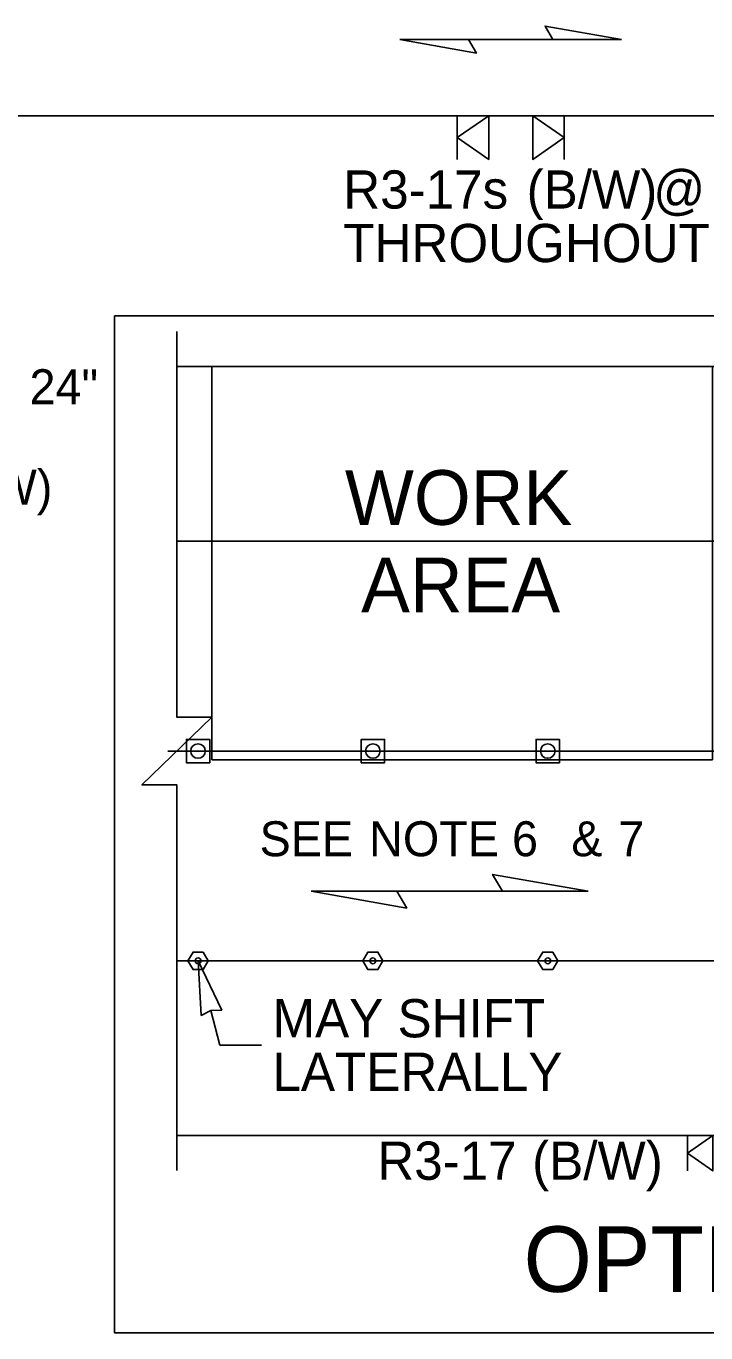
# Model space of a CAD drawing. Extents: x 99999.1 to 100095.7, y 99995 to 100010.7.
# Drawn here: x 100045 to 100046.244, y 100003.505 to 100005.896 of the extents above; entities that cross this region are included whole.
import ezdxf

# ---------------------------------------------------------------- set-up
doc = ezdxf.new("R2010")
doc.units = 0
for name, color, linetype in [('RD_ED_ShoulderPavedEdge', 7, 'Continuous'), ('RD_MK_LineEdgeWhite', 7, 'Continuous'), ('RD_MK_LineSkipCenter', 7, 'Continuous'), ('SH_DE_DetailHeading2Text', 7, 'Continuous'), ('SH_TI_Tables', 7, 'Continuous'), ('TR_SN_ConstructionSigns', 7, 'Continuous'), ('TR_WZ_PortableSignMountBlk-Wht', 7, 'Continuous'), ('TR_WZ_TrafficCone', 7, 'Continuous'), ('TR_WZ_TubularMarker', 7, 'Continuous'), ('TR_WZ_WorkAreaLabel', 7, 'Continuous'), ('TR_WZ_WorkZoneDetails', 7, 'Continuous'), ('TR_WZ_WorkZoneTextCurrent', 7, 'Continuous')]:
    doc.layers.add(name, color=color, linetype=linetype)

msp = doc.modelspace()

# ---------------------------------------------------------------- linework, layer by layer
at = {"layer": 'RD_ED_ShoulderPavedEdge'}
for p, q in [((100040.1076, 100005.7323), (100055.6424, 100005.7323)), ((100045.2759, 100005.2735), (100049.1933, 100005.2735)), ((100045.2759, 100003.8655), (100049.1933, 100003.8655))]:
    msp.add_line(p, q, dxfattribs=at)
at = {"layer": 'RD_MK_LineEdgeWhite'}
for p, q in [((100045.2759, 100004.9535), (100049.1933, 100004.9535)), ((100045.2759, 100004.1855), (100049.1933, 100004.1855))]:
    msp.add_line(p, q, dxfattribs=at)
at = {"layer": 'RD_MK_LineSkipCenter'}
msp.add_lwpolyline([(100049.1767, 100004.5695), (100045.2594, 100004.5695)], dxfattribs=at)
at = {"layer": 'SH_TI_Tables'}
msp.add_lwpolyline([(100045.1619, 100005.3662), (100049.3073, 100005.3662), (100049.3073, 100003.5045), (100045.1619, 100003.5045)], close=True, dxfattribs=at)
at = {"layer": 'TR_WZ_PortableSignMountBlk-Wht'}
for p, q in [((100045.7891, 100005.6523), (100045.7891, 100005.7323)), ((100045.9846, 100005.6523), (100045.9846, 100005.7323)), ((100046.2103, 100003.8011), (100046.2103, 100003.8655))]:
    msp.add_line(p, q, dxfattribs=at)
for points in [[(100045.7891, 100005.6923), (100045.8465, 100005.7323), (100045.8465, 100005.6523)], [(100045.9846, 100005.6923), (100045.9271, 100005.7323), (100045.9271, 100005.6523)], [(100046.2103, 100003.8333), (100046.2565, 100003.8655), (100046.2565, 100003.8011)]]:
    msp.add_lwpolyline(points, close=True, dxfattribs=at)
at = {"layer": 'TR_WZ_TrafficCone'}
for points in [[(100045.2933, 100004.5908), (100045.3359, 100004.5908), (100045.3359, 100004.5482), (100045.2933, 100004.5482), (100045.2933, 100004.5908)], [(100045.2933, 100004.5482), (100045.3359, 100004.5482), (100045.3359, 100004.5908), (100045.2933, 100004.5908), (100045.2933, 100004.5482)], [(100045.6133, 100004.5908), (100045.6559, 100004.5908), (100045.6559, 100004.5482), (100045.6133, 100004.5482), (100045.6133, 100004.5908)], [(100045.6133, 100004.5482), (100045.6559, 100004.5482), (100045.6559, 100004.5908), (100045.6133, 100004.5908), (100045.6133, 100004.5482)], [(100045.9333, 100004.5908), (100045.9759, 100004.5908), (100045.9759, 100004.5482), (100045.9333, 100004.5482), (100045.9333, 100004.5908)], [(100045.9333, 100004.5482), (100045.9759, 100004.5482), (100045.9759, 100004.5908), (100045.9333, 100004.5908), (100045.9333, 100004.5482)]]:
    msp.add_lwpolyline(points, dxfattribs=at)
for centre in [(100045.3146, 100004.5695), (100045.6346, 100004.5695), (100045.9546, 100004.5695)]:
    msp.add_circle(centre, 0.0133, dxfattribs=at)
at = {"layer": 'TR_WZ_TubularMarker'}
for points in [[(100045.2961, 100004.1855), (100045.3054, 100004.2015), (100045.3239, 100004.2015), (100045.3331, 100004.1855), (100045.3239, 100004.1695), (100045.3054, 100004.1695)], [(100045.6161, 100004.1855), (100045.6254, 100004.2015), (100045.6438, 100004.2015), (100045.6531, 100004.1855), (100045.6438, 100004.1695), (100045.6254, 100004.1695)], [(100045.9361, 100004.1855), (100045.9454, 100004.2015), (100045.9638, 100004.2015), (100045.9731, 100004.1855), (100045.9638, 100004.1695), (100045.9454, 100004.1695)]]:
    msp.add_lwpolyline(points, close=True, dxfattribs=at)
for points in [[(100045.3054, 100004.1695), (100045.3239, 100004.1695), (100045.3331, 100004.1855), (100045.3239, 100004.2015), (100045.3054, 100004.2015), (100045.2961, 100004.1855), (100045.3054, 100004.1695)], [(100045.6254, 100004.1695), (100045.6438, 100004.1695), (100045.6531, 100004.1855), (100045.6438, 100004.2015), (100045.6254, 100004.2015), (100045.6161, 100004.1855), (100045.6254, 100004.1695)], [(100045.9454, 100004.1695), (100045.9638, 100004.1695), (100045.9731, 100004.1855), (100045.9638, 100004.2015), (100045.9454, 100004.2015), (100045.9361, 100004.1855), (100045.9454, 100004.1695)]]:
    msp.add_lwpolyline(points, dxfattribs=at)
for centre in [(100045.3146, 100004.1855), (100045.6346, 100004.1855), (100045.9546, 100004.1855)]:
    msp.add_circle(centre, 0.00533, dxfattribs=at)
at = {"layer": 'TR_WZ_WorkZoneDetails'}
for p, q in [((100045.964, 100005.8716), (100045.8097, 100005.8716)), ((100045.8097, 100005.8716), (100045.964, 100005.8716)), ((100045.6787, 100004.3129), (100045.8716, 100004.3129)), ((100045.8716, 100004.3129), (100045.6787, 100004.3129)), ((100045.3382, 100004.0948), (100045.3546, 100004.0314)), ((100045.4308, 100004.0314), (100045.3546, 100004.0314))]:
    msp.add_line(p, q, dxfattribs=at)
for points in [[(100046.0898, 100005.8716), (100045.9497, 100005.8963), (100045.964, 100005.8716)], [(100045.6839, 100005.8716), (100045.824, 100005.8469), (100045.8097, 100005.8716)], [(100045.3399, 100005.2735), (100045.3399, 100004.5535), (100046.2559, 100004.5535), (100046.2559, 100005.2735)], [(100046.0288, 100004.3129), (100045.8537, 100004.3438), (100045.8716, 100004.3129)], [(100045.5214, 100004.3129), (100045.6965, 100004.2821), (100045.6787, 100004.3129)], [(100045.3146, 100004.1855), (100045.3579, 100004.0952), (100045.3381, 100004.0948), (100045.3206, 100004.0855)]]:
    msp.add_lwpolyline(points, close=True, dxfattribs=at)
msp.add_lwpolyline([(100045.2759, 100003.8015), (100045.2759, 100004.5075), (100045.2119, 100004.5075), (100045.3399, 100004.6314), (100045.2759, 100004.6314), (100045.2759, 100005.3375)], dxfattribs=at)

# ---------------------------------------------------------------- texts
at = {"layer": 'SH_DE_DetailHeading2Text'}
msp.add_text('OPTIONAL LANE SHIFT DETAIL', height=0.12, rotation=360, dxfattribs=at).set_placement((100045.9105, 100003.5795))
at = {"layer": 'TR_SN_ConstructionSigns'}
for s, p in [('24"', (100045.0062, 100005.2043)), ('R3-17 (B/W)', (100044.5725, 100005.0203))]:
    msp.add_text(s, height=0.064, rotation=360, dxfattribs=at).set_placement(p)
at = {"layer": 'TR_WZ_WorkAreaLabel'}
for s, p in [('WORK', (100045.5834, 100004.9835)), ('AREA', (100045.6131, 100004.8235))]:
    msp.add_text(s, height=0.1, dxfattribs=at).set_placement(p)
at = {"layer": 'TR_WZ_WorkZoneDetails'}
for s, p in [('R3-17s', (100045.5804, 100005.5623)), ('(B/W)', (100045.916, 100005.5623)), (' @', (100046.1218, 100005.5623)), ('THROUGHOUT LANE CLOSURE', (100045.5804, 100005.4643)), ('R3-17', (100045.6427, 100003.7847)), ('(B/W)', (100045.9261, 100003.7847))]:
    msp.add_text(s, height=0.07, rotation=360, dxfattribs=at).set_placement(p)
at = {"layer": 'TR_WZ_WorkZoneTextCurrent'}
for s, height, p in [('SEE', 0.064, (100045.4272, 100004.3769)), ('NOTE 6', 0.064, (100045.6277, 100004.3769)), ('&', 0.064, (100045.9978, 100004.3769)), ('7', 0.064, (100046.0836, 100004.3769)), ('MAY SHIFT', 0.07, (100045.4508, 100004.0454)), ('LATERALLY', 0.07, (100045.4508, 100003.9474))]:
    msp.add_text(s, height=height, dxfattribs=at).set_placement(p)

doc.saveas('drawing.dxf')
